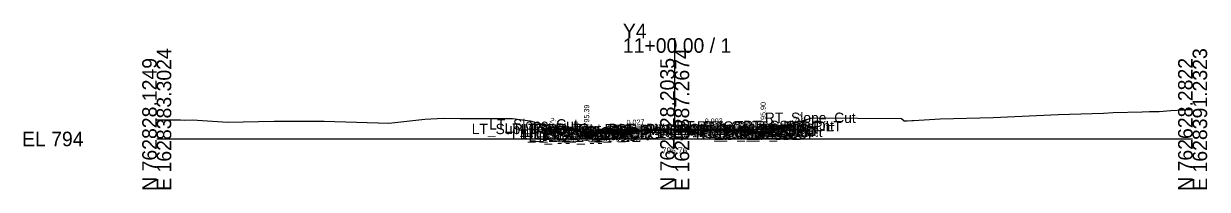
# Model space of a CAD drawing. Extents: x -26 to 203, y -10 to 3017.
# Drawn here: x -25.7 to 202.8, y 1990.3 to 2022.2 of the extents above; entities that cross this region are included whole.
import ezdxf

# ---------------------------------------------------------------- set-up
doc = ezdxf.new("R2010")
doc.units = 0
for name, color, linetype in [('Default', 7, 'Continuous'), ('Exist CMT Pavement', 7, 'Continuous'), ('Exist Cross Section Cell', 7, 'Continuous'), ('Exist XS Center Line Elevation Label', 7, 'Continuous'), ('Exist XS Ground Line', 7, 'Continuous'), ('Prop CMT Conc Surface', 7, 'Continuous'), ('Prop CMT Concrete Structures', 7, 'Continuous'), ('Prop CMT Pvmt Course 1', 7, 'Continuous'), ('Prop CMT Pvmt Course 1 CG', 7, 'Continuous'), ('Prop CMT Pvmt Course 1 Wedge', 7, 'Continuous'), ('Prop CMT Pvmt Course 2', 7, 'Continuous'), ('Prop CMT Pvmt Course 2 Wedge', 7, 'Continuous'), ('Prop CMT Pvmt Course 3', 7, 'Continuous'), ('Prop CMT Pvmt Surface', 7, 'Continuous'), ('Prop CMT Pvmt Wedge Surface 1', 7, 'Continuous'), ('Prop CMT Pvmt Wedge Surface 2', 7, 'Continuous'), ('Prop CMT Pvmt Wedge Surface 3', 7, 'Continuous'), ('Prop CMT Slope Grass', 7, 'Continuous'), ('Prop CMT Subgrade Earthwork', 7, 'Continuous'), ('Prop XS Hydro Elevations', 7, 'Continuous'), ('Prop XS SE Text', 7, 'Continuous'), ('Prop XS Side Slope Text', 7, 'Continuous'), ('Scratch_Level_0', 7, 'Continuous')]:
    doc.layers.add(name, color=color, linetype=linetype)

msp = doc.modelspace()

# ---------------------------------------------------------------- linework, layer by layer
at = {"layer": 'Exist CMT Pavement'}
for points in [[(100, 2001.76), (99.91, 2001.76), (99.62, 2001.75), (89.08, 2001.28), (88.52, 2001.24), (85.12, 2000.98)], [(100, 2001.76), (100.16, 2001.76), (111, 2001.62), (112.2, 2001.56), (114.91, 2001.46)]]:
    msp.add_lwpolyline(points, dxfattribs=at)
at = {"layer": 'Exist Cross Section Cell'}
for p, q in [((100, 2000), (100, 2019.4)), ((0, 2000), (100, 2000)), ((100, 2000), (200, 2000))]:
    msp.add_line(p, q, dxfattribs=at)
at = {"layer": 'Exist XS Ground Line'}
msp.add_lwpolyline([(0, 2003.69), (4.58, 2003.67), (5.31, 2003.65), (6.93, 2003.66), (13.65, 2003.24), (22.69, 2003.44), (32.31, 2003.43), (44.78, 2003.02), (51.77, 2003.79), (55.28, 2003.98), (58.6, 2003.95), (68.66, 2003.97), (72.07, 2003.48), (76.28, 2002.34), (78.46, 2001.77), (78.81, 2001.75), (84.08, 2001.3), (84.66, 2001.23), (85.12, 2000.98), (88.52, 2001.24), (89.08, 2001.28), (99.91, 2001.76), (111, 2001.62), (112.2, 2001.56), (114.91, 2001.46), (115.39, 2001.84), (116.16, 2001.85), (118.84, 2001.85), (125.88, 2003.87), (126.63, 2004.08), (126.95, 2004.09), (143.78, 2003.97), (144.28, 2003.47), (144.86, 2003.51), (145.78, 2003.56), (146.12, 2003.57), (151.24, 2003.89), (161.52, 2004.12), (174.05, 2004.74), (182.8, 2004.99), (184.67, 2005.11), (190.25, 2005.24), (191.68, 2005.27), (193.57, 2005.32), (195.82, 2005.5), (198.26, 2005.63), (200, 2005.67)], dxfattribs=at)
at = {"layer": 'Prop CMT Conc Surface'}
for points in [[(115.08, 2001.97), (117.08, 2001.9)], [(117.08, 2001.9), (117.08, 2002.4), (117.58, 2002.4)], [(83, 2001.39), (83, 2001.89), (82.5, 2001.89)], [(85, 2001.52), (83, 2001.39)]]:
    msp.add_lwpolyline(points, dxfattribs=at)
at = {"layer": 'Prop CMT Concrete Structures'}
for points in [[(115.08, 2001.97), (117.08, 2001.9), (117.08, 2002.4), (117.58, 2002.4)], [(117.58, 2002.4), (117.58, 2001.39), (115.08, 2001.39)], [(115.08, 2001.39), (115.08, 2001.97)], [(117.58, 2002.4), (117.58, 2002.06)], [(117.58, 2002.06), (122.58, 2002.16)], [(122.58, 2002.16), (122.58, 2002.5)], [(85, 2001.52), (83, 2001.39), (83, 2001.89), (82.5, 2001.89)], [(82.5, 2001.89), (82.5, 2000.87), (85, 2000.94)], [(85, 2000.94), (85, 2001.52)]]:
    msp.add_lwpolyline(points, dxfattribs=at)
at = {"layer": 'Prop CMT Pvmt Course 1'}
for points in [[(100, 2001.93), (115.08, 2001.97)], [(115.08, 2001.97), (115.08, 2001.72)], [(100, 2001.93), (85, 2001.52)], [(85, 2001.52), (85, 2001.27)], [(85, 2001.27), (85.12, 2001.27)], [(85.12, 2001.4), (100, 2001.8)], [(85.12, 2001.27), (85.12, 2001.4)], [(100, 2001.68), (100, 2001.93)], [(100, 2001.68), (100, 2001.93)], [(114.91, 2001.84), (100, 2001.8)], [(100, 2001.8), (100, 2001.68), (100, 2001.68)], [(100, 2001.8), (100, 2001.68), (100, 2001.68)], [(114.91, 2001.72), (114.91, 2001.84)], [(115.08, 2001.72), (114.91, 2001.72)]]:
    msp.add_lwpolyline(points, dxfattribs=at)
at = {"layer": 'Prop CMT Pvmt Course 1 CG'}
for points in [[(85, 2000.94), (82, 2000.85), (81.66, 2000.51)], [(81.66, 2000.51), (85, 2000.6)], [(85, 2000.6), (85, 2000.94)], [(115.08, 2001.39), (118.08, 2001.39), (118.41, 2001.06)], [(115.08, 2001.05), (115.08, 2001.39)], [(118.41, 2001.06), (115.08, 2001.05)]]:
    msp.add_lwpolyline(points, dxfattribs=at)
at = {"layer": 'Prop CMT Pvmt Course 1 Wedge'}
for points in [[(85.12, 2001.4), (88.52, 2001.49), (89.08, 2001.51), (99.62, 2001.79), (99.91, 2001.8), (100, 2001.8)], [(100, 2001.76), (99.91, 2001.76), (99.62, 2001.75), (94.94, 2001.54), (89.08, 2001.38), (88.52, 2001.36), (85.12, 2001.27)], [(85.12, 2001.4), (85.12, 2001.4)], [(85.12, 2001.27), (85.12, 2001.4)], [(85.12, 2001.27), (85.12, 2001.27)], [(100, 2001.8), (100.16, 2001.8), (111, 2001.83), (112.2, 2001.84), (114.91, 2001.84)], [(100, 2001.8), (100, 2001.76)], [(100, 2001.76), (100, 2001.8)], [(114.91, 2001.72), (112.2, 2001.71), (111, 2001.71), (105.25, 2001.69), (100.16, 2001.76), (100, 2001.76)], [(114.91, 2001.84), (114.91, 2001.72)]]:
    msp.add_lwpolyline(points, dxfattribs=at)
at = {"layer": 'Prop CMT Pvmt Course 2'}
for points in [[(85.12, 2001.27), (85, 2001.27)], [(85, 2001.27), (85, 2000.94)], [(85, 2000.94), (85.12, 2000.94)], [(85.12, 2000.94), (85.12, 2001.27)], [(114.91, 2001.39), (114.91, 2001.72)], [(114.91, 2001.72), (115.08, 2001.72)], [(115.08, 2001.39), (114.91, 2001.39)], [(115.08, 2001.72), (115.08, 2001.39)]]:
    msp.add_lwpolyline(points, dxfattribs=at)
at = {"layer": 'Prop CMT Pvmt Course 2 Wedge'}
for points in [[(85.12, 2001.27), (88.52, 2001.36), (89.08, 2001.38), (94.94, 2001.54)], [(94.94, 2001.54), (89.08, 2001.28), (88.52, 2001.24), (85.12, 2000.98)], [(85.12, 2001.27), (85.12, 2001.27)], [(85.12, 2000.98), (85.12, 2001.27)], [(85.12, 2000.98), (85.12, 2000.98)], [(105.25, 2001.69), (111, 2001.71)], [(114.91, 2001.46), (112.2, 2001.56), (111, 2001.62), (105.25, 2001.69)], [(111, 2001.71), (112.2, 2001.71), (114.91, 2001.72)], [(114.91, 2001.72), (114.91, 2001.46)]]:
    msp.add_lwpolyline(points, dxfattribs=at)
at = {"layer": 'Prop CMT Pvmt Course 3'}
for points in [[(85.12, 2000.94), (85, 2000.94)], [(85, 2000.94), (85, 2000.6)], [(85, 2000.6), (85.12, 2000.61)], [(85.12, 2000.61), (85.12, 2000.94)], [(114.91, 2001.39), (115.08, 2001.39)], [(114.91, 2001.05), (114.91, 2001.39)], [(115.08, 2001.05), (114.91, 2001.05)], [(115.08, 2001.39), (115.08, 2001.05)]]:
    msp.add_lwpolyline(points, dxfattribs=at)
at = {"layer": 'Prop CMT Pvmt Surface'}
for points in [[(100, 2001.93), (115.08, 2001.97)], [(100, 2001.93), (85, 2001.52)]]:
    msp.add_lwpolyline(points, dxfattribs=at)
at = {"layer": 'Prop CMT Pvmt Wedge Surface 1'}
for points in [[(115.08, 2001.72), (115.08, 2001.97)], [(85, 2001.27), (85, 2001.52)], [(85.12, 2001.27), (85, 2001.27)], [(100, 2001.8), (85.12, 2001.4)], [(85.12, 2001.4), (85.12, 2001.27)], [(100, 2001.8), (114.91, 2001.84)], [(114.91, 2001.84), (114.91, 2001.72)], [(114.91, 2001.72), (115.08, 2001.72)]]:
    msp.add_lwpolyline(points, dxfattribs=at)
at = {"layer": 'Prop CMT Pvmt Wedge Surface 2'}
for points in [[(115.08, 2001.72), (115.08, 2001.97)], [(100, 2001.68), (85, 2001.27)], [(85, 2001.27), (85, 2001.52)], [(100, 2001.68), (115.08, 2001.72)]]:
    msp.add_lwpolyline(points, dxfattribs=at)
at = {"layer": 'Prop CMT Pvmt Wedge Surface 3'}
for points in [[(115.08, 2001.39), (115.08, 2001.97)], [(85, 2000.94), (85, 2001.52)], [(100, 2001.34), (85, 2000.94)], [(100, 2001.34), (115.08, 2001.39)]]:
    msp.add_lwpolyline(points, dxfattribs=at)
at = {"layer": 'Prop CMT Slope Grass'}
for p, q in [((76.33, 2002.33), (77, 2002)), ((123.08, 2002.51), (125.74, 2003.83))]:
    msp.add_line(p, q, dxfattribs=at)
for points in [[(82.5, 2001.89), (77, 2002)], [(117.58, 2002.4), (123.08, 2002.51)]]:
    msp.add_lwpolyline(points, dxfattribs=at)
at = {"layer": 'Prop CMT Subgrade Earthwork'}
for points in [[(115.08, 2001.05), (118.41, 2001.06), (119.45, 2002.1)], [(85, 2000.6), (81.66, 2000.51), (80.24, 2001.93)], [(85.12, 2000.61), (85, 2000.6)], [(85.12, 2000.61), (85.13, 2000.98)], [(114.91, 2001.05), (114.89, 2001.46)], [(114.91, 2001.05), (115.08, 2001.05)]]:
    msp.add_lwpolyline(points, dxfattribs=at)

# ---------------------------------------------------------------- texts
at = {"layer": 'Default'}
msp.add_text('-', height=0.0001, dxfattribs=at).set_placement((0, 2000))
at = {"layer": 'Exist Cross Section Cell'}
for s, p in [('Y4', (90, 2019.4)), ('11+00.00 / 1', (90, 2016.6)), ('EL 794', (-26, 1998.6))]:
    msp.add_text(s, height=2.8, dxfattribs=at).set_placement(p)
for s, p in [('E 1628383.3024', (2.8, 1990)), ('E 1628387.2674', (102.8, 1990)), ('E 1628391.2323', (202.8, 1990)), ('N 762828.1249', (0, 1990)), ('N 762728.2035', (100, 1990)), ('N 762628.2822', (200, 1990))]:
    msp.add_text(s, height=2.8, rotation=90, dxfattribs=at).set_placement(p)
at = {"layer": 'Exist XS Center Line Elevation Label'}
msp.add_text('795.76', height=1.2, dxfattribs=at).set_placement((97.52, 1997.16))
at = {"layer": 'Prop XS Hydro Elevations'}
for s, p in [('795.90', (117.58, 2002.9)), ('795.39', (83.5, 2002.39))]:
    msp.add_text(s, height=1, rotation=90, dxfattribs=at).set_placement(p)
at = {"layer": 'Prop XS SE Text'}
for s, rotation, p in [('0.027', 1.5548, (90.72, 2002.67)), ('0.003', 0.1637, (105.81, 2002.94))]:
    msp.add_text(s, height=1, rotation=rotation, dxfattribs=at).set_placement(p)
at = {"layer": 'Prop XS Side Slope Text'}
for rotation, p in [(26.5651, (123.27, 2003.18)), (333.4349, (75.77, 2003.3))]:
    msp.add_text('2:1', height=1, rotation=rotation, dxfattribs=at).set_placement(p)
at = {"layer": 'Scratch_Level_0'}
for s, p in [('RT_Slope_Cut', (117.41, 2003.08)), ('LT_Sub_Trench_Out_DLT', (60.81, 2000.93)), ('LT_Slope_Cut', (64.19, 2001.81)), ('LT_CSLP_Pnt', (67.17, 2001)), ('LT_CG1_Shelf_Out', (68.55, 1999.85)), ('LT_PV_Sub_Tie_Out', (70.08, 1999.98)), ('LT_CG_Top_Face', (70.26, 2000.89)), ('LT_CG_Top_BOC', (70.78, 2000.89)), ('LT_CG_Top_Gut', (71.24, 2000.39)), ('LT_PV_OEEOP_EG', (72.66, 1999.98)), ('LT_PV2_OEEOP', (74.43, 2000.27)), ('LT_PV3_OEEOP', (74.43, 1999.94)), ('LT_CG_Bot_IE', (74.91, 1999.94)), ('LT_PV1_OEEOP', (74.99, 2000.4)), ('LT_PV2_OEOT', (75.17, 2000.27)), ('LT_PV3_OEOT', (75.17, 1999.94)), ('LT_PV1_OEOT', (75.74, 2000.52)), ('RT_PV_IEEOP_EG', (88.14, 2000.76)), ('LT_PV_IEEOP_EG', (88.19, 2000.76)), ('RT_PV2_IEEOP', (89.91, 2000.68)), ('RT_PV3_IEEOP', (89.91, 2000.34)), ('LT_PV2_IEEOP', (89.95, 2000.68)), ('LT_PV3_IEEOP', (89.95, 2000.34)), ('RT_PV1_IEEOP', (90.47, 2000.8)), ('LT_PV1_IEEOP', (90.52, 2000.8)), ('PV2_PGL', (93.91, 2000.68)), ('PV1_PGL', (94.47, 2000.93)), ('RT_PV_Sub_Tie_Out', (99.79, 2000.46)), ('RT_Sub_Trench_Out_DLT', (100.31, 2001.44)), ('RT_PV_OEEOP_EG', (102.4, 2000.46)), ('RT_Sub_OEEOP', (104.07, 2000.05)), ('RT_PV2_OEEOP', (104.17, 2000.72)), ('RT_PV3_OEEOP', (104.17, 2000.39)), ('RT_CG_Top_Face', (104.3, 2001.4)), ('RT_CG1_Shelf_Out', (104.59, 2000.39)), ('RT_PV1_OEEOP', (104.73, 2000.84)), ('RT_CG_Bot_IE', (104.95, 2000.39)), ('RT_Sub_OEOT', (105.11, 2000.05)), ('RT_PV2_OEOT', (105.21, 2000.72)), ('RT_PV3_OEOT', (105.21, 2000.39)), ('RT_CG_Top_Gut', (105.27, 2000.9)), ('RT_PV1_OEOT', (105.77, 2000.97)), ('RT_CG_Top_BOC', (105.82, 2001.4)), ('RT_CG_Bot_BOC', (105.85, 2000.39)), ('RT_Sub_OEOP', (108.48, 2000.06)), ('RT_CSLP_Pnt', (113.21, 2001.51)), ('LT_CG_Bot_BOC', (70.81, 1999.87)), ('LT_Sub_OEOP', (71.77, 1999.51)), ('LT_Sub_OEEOP', (74.33, 1999.61)), ('LT_Sub_OEOT', (75.08, 1999.6))]:
    msp.add_text(s, height=2, dxfattribs=at).set_placement(p)

doc.saveas('drawing.dxf')
